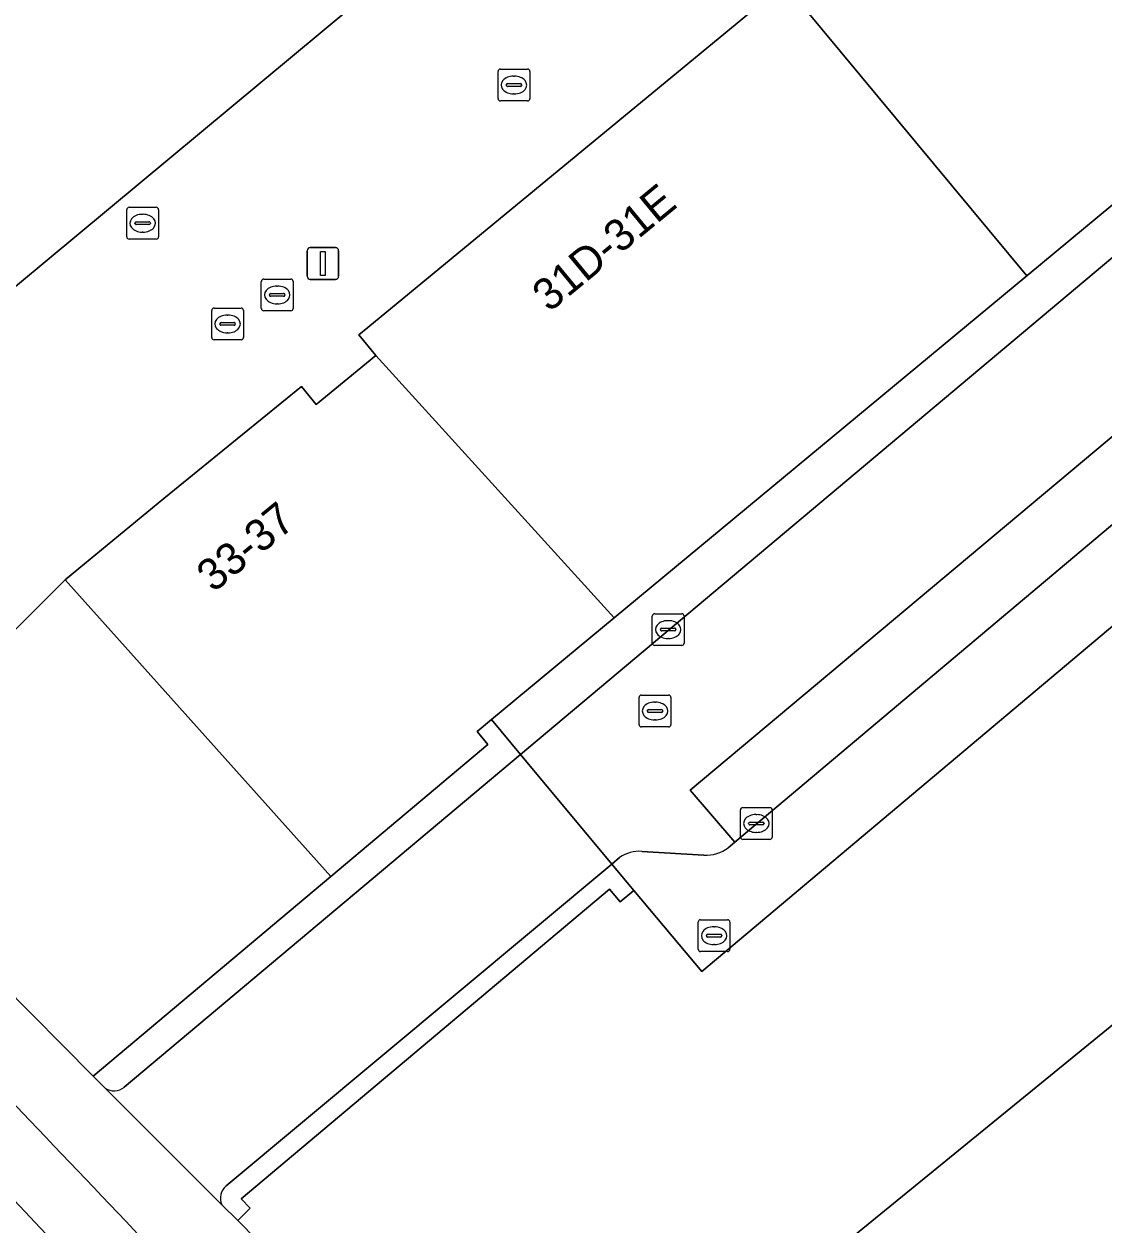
# Model space of a CAD drawing. Extents: x 161087 to 161926, y 382572 to 383873.
# Drawn here: x 161249.19 to 161283.16, y 383145.33 to 383183.09 of the extents above; entities that cross this region are included whole.
import ezdxf

# ---------------------------------------------------------------- set-up
doc = ezdxf.new("R2010")
doc.units = 0
for name, color, linetype in [('IMGEO_Berm_open', 7, 'Continuous'), ('IMGEO_Fietspad_gesloten', 7, 'Continuous'), ('IMGEO_Kolk', 7, 'Continuous'), ('IMGEO_Lichtmast', 7, 'Continuous'), ('IMGEO_Pand', 7, 'Continuous'), ('IMGEO_Pand_nummerreeks', 7, 'Continuous'), ('IMGEO_Pand_overbouw', 7, 'Continuous'), ('IMGEO_Parkeervlak_open', 7, 'Continuous'), ('IMGEO_Rijbaan_lokaal_open', 7, 'Continuous'), ('IMGEO_Rioolput', 7, 'Continuous'), ('IMGEO_Voetgangersgebied_open', 7, 'Continuous'), ('IMGEO_Voetpad_open', 7, 'Continuous')]:
    doc.layers.add(name, color=color, linetype=linetype)

msp = doc.modelspace()

# ---------------------------------------------------------------- linework, layer by layer
at = {"layer": 'IMGEO_Berm_open'}
msp.add_lwpolyline([(161247.064, 383148.001), (161242.001, 383153.229), (161238.837, 383153.269), (161246.469, 383145.394), (161245.035, 383144.043), (161249.891, 383139.013), (161252.834, 383141.869)], close=True, dxfattribs=at)
at = {"layer": 'IMGEO_Fietspad_gesloten'}
msp.add_lwpolyline([(161249.369, 383148.585), (161245.087, 383153.075), (161241.034, 383157.27), (161239.46, 383155.862), (161242.001, 383153.229), (161247.064, 383148.001), (161252.834, 383141.869), (161255.215, 383139.338), (161259.245, 383134.997), (161263.4, 383130.521)], dxfattribs=at)
msp.add_arc((160590.35, 382517.9), 912.178, 42.27546, 43.741408, dxfattribs=at)
at = {"layer": 'IMGEO_Kolk'}
for p, q in [((161264.101, 383180.745), (161264.101, 383181.597)), ((161264.176, 383181.671), (161265.028, 383181.671)), ((161265.102, 383181.597), (161265.102, 383180.745)), ((161264.36, 383181.165), (161264.36, 383181.177)), ((161264.403, 383181.214), (161264.801, 383181.214)), ((161264.589, 383181.451), (161264.614, 383181.451)), ((161264.844, 383181.177), (161264.844, 383181.165)), ((161264.798, 383181.128), (161264.4, 383181.128)), ((161264.612, 383180.891), (161264.587, 383180.891)), ((161265.028, 383180.671), (161264.176, 383180.671)), ((161252.419, 383176.396), (161252.419, 383177.248)), ((161252.494, 383177.322), (161253.346, 383177.322)), ((161252.907, 383177.102), (161252.932, 383177.102)), ((161253.42, 383177.248), (161253.42, 383176.396)), ((161252.678, 383176.816), (161252.678, 383176.828)), ((161253.116, 383176.779), (161252.718, 383176.779)), ((161252.721, 383176.865), (161253.119, 383176.865)), ((161253.162, 383176.828), (161253.162, 383176.816)), ((161253.346, 383176.322), (161252.494, 383176.322)), ((161252.93, 383176.542), (161252.905, 383176.542)), ((161255.091, 383173.226), (161255.091, 383174.078)), ((161255.166, 383174.152), (161256.018, 383174.152)), ((161256.092, 383174.078), (161256.092, 383173.226)), ((161255.35, 383173.646), (161255.35, 383173.658)), ((161255.788, 383173.609), (161255.39, 383173.609)), ((161255.393, 383173.695), (161255.791, 383173.695)), ((161255.579, 383173.932), (161255.604, 383173.932)), ((161255.834, 383173.658), (161255.834, 383173.646)), ((161255.602, 383173.372), (161255.577, 383173.372)), ((161256.018, 383173.152), (161255.166, 383173.152)), ((161268.953, 383163.609), (161268.953, 383164.461)), ((161269.028, 383164.535), (161269.88, 383164.535)), ((161269.441, 383164.315), (161269.466, 383164.315)), ((161269.954, 383164.461), (161269.954, 383163.609)), ((161269.212, 383164.029), (161269.212, 383164.041)), ((161269.65, 383163.992), (161269.252, 383163.992)), ((161269.255, 383164.078), (161269.653, 383164.078)), ((161269.696, 383164.041), (161269.696, 383164.029)), ((161269.88, 383163.535), (161269.028, 383163.535)), ((161269.464, 383163.755), (161269.439, 383163.755)), ((161271.726, 383157.507), (161271.726, 383158.359)), ((161271.801, 383158.433), (161272.653, 383158.433)), ((161272.214, 383158.213), (161272.239, 383158.213)), ((161272.727, 383158.359), (161272.727, 383157.507)), ((161271.985, 383157.927), (161271.985, 383157.939)), ((161272.423, 383157.89), (161272.025, 383157.89)), ((161272.028, 383157.976), (161272.426, 383157.976)), ((161272.469, 383157.939), (161272.469, 383157.927)), ((161272.653, 383157.433), (161271.801, 383157.433)), ((161272.237, 383157.653), (161272.212, 383157.653))]:
    msp.add_line(p, q, dxfattribs=at)
for points in [[(161264.101, 383180.745), (161264.101, 383181.597)], [(161264.176, 383181.671), (161265.028, 383181.671)], [(161265.102, 383181.597), (161265.102, 383180.745)], [(161265.028, 383180.671), (161264.176, 383180.671)], [(161252.419, 383176.396), (161252.419, 383177.248)], [(161252.494, 383177.322), (161253.346, 383177.322)], [(161253.42, 383177.248), (161253.42, 383176.396)], [(161253.346, 383176.322), (161252.494, 383176.322)], [(161255.091, 383173.226), (161255.091, 383174.078)], [(161255.166, 383174.152), (161256.018, 383174.152)], [(161256.092, 383174.078), (161256.092, 383173.226)], [(161256.018, 383173.152), (161255.166, 383173.152)], [(161268.953, 383163.609), (161268.953, 383164.461)], [(161269.028, 383164.535), (161269.88, 383164.535)], [(161269.954, 383164.461), (161269.954, 383163.609)], [(161269.88, 383163.535), (161269.028, 383163.535)], [(161271.726, 383157.507), (161271.726, 383158.359)], [(161271.801, 383158.433), (161272.653, 383158.433)], [(161272.727, 383158.359), (161272.727, 383157.507)], [(161272.653, 383157.433), (161271.801, 383157.433)]]:
    msp.add_lwpolyline(points, dxfattribs=at)
for centre, radius, start, end in [((161264.178, 383181.595), 0.0765, 91.552, 178.448), ((161264.178, 383181.595), 0.0765, 91.552, 178.448), ((161265.026, 383181.595), 0.0765, 1.552, 88.448), ((161265.026, 383181.595), 0.0765, 1.552, 88.448), ((161264.4, 383181.174), 0.0403, 85.8775, 175.7526), ((161264.397, 383181.164), 0.0366, 178.938, 274.7102), ((161264.801, 383181.171), 0.043, 264.8664, 352.4533), ((161264.805, 383181.176), 0.0386, 1.7309, 96.639), ((161264.178, 383180.747), 0.0765, 181.552, 268.448), ((161264.178, 383180.747), 0.0765, 181.552, 268.448), ((161265.026, 383180.747), 0.0765, 271.552, 358.448), ((161265.026, 383180.747), 0.0765, 271.552, 358.448), ((161252.496, 383177.246), 0.0765, 91.552, 178.448), ((161252.496, 383177.246), 0.0765, 91.552, 178.448), ((161253.344, 383177.246), 0.0765, 1.552, 88.448), ((161253.344, 383177.246), 0.0765, 1.552, 88.448), ((161252.718, 383176.825), 0.0403, 85.8775, 175.7526), ((161252.715, 383176.815), 0.0366, 178.938, 274.7102), ((161253.119, 383176.822), 0.043, 264.8664, 352.4533), ((161253.123, 383176.827), 0.0386, 1.7309, 96.639), ((161252.496, 383176.398), 0.0765, 181.552, 268.448), ((161252.496, 383176.398), 0.0765, 181.552, 268.448), ((161253.344, 383176.398), 0.0765, 271.552, 358.448), ((161253.344, 383176.398), 0.0765, 271.552, 358.448), ((161255.168, 383174.076), 0.0765, 91.552, 178.448), ((161255.168, 383174.076), 0.0765, 91.552, 178.448), ((161256.016, 383174.076), 0.0765, 1.552, 88.448), ((161256.016, 383174.076), 0.0765, 1.552, 88.448), ((161255.39, 383173.655), 0.0403, 85.8775, 175.7526), ((161255.387, 383173.645), 0.0366, 178.938, 274.7102), ((161255.791, 383173.652), 0.043, 264.8664, 352.4533), ((161255.795, 383173.657), 0.0386, 1.7309, 96.639), ((161255.168, 383173.228), 0.0765, 181.552, 268.448), ((161255.168, 383173.228), 0.0765, 181.552, 268.448), ((161256.016, 383173.228), 0.0765, 271.552, 358.448), ((161256.016, 383173.228), 0.0765, 271.552, 358.448), ((161269.03, 383164.459), 0.0765, 91.552, 178.448), ((161269.03, 383164.459), 0.0765, 91.552, 178.448), ((161269.878, 383164.459), 0.0765, 1.552, 88.448), ((161269.878, 383164.459), 0.0765, 1.552, 88.448), ((161269.252, 383164.038), 0.0403, 85.8775, 175.7526), ((161269.249, 383164.028), 0.0366, 178.938, 274.7102), ((161269.653, 383164.035), 0.043, 264.8664, 352.4533), ((161269.657, 383164.04), 0.0386, 1.7309, 96.639), ((161269.03, 383163.611), 0.0765, 181.552, 268.448), ((161269.03, 383163.611), 0.0765, 181.552, 268.448), ((161269.878, 383163.611), 0.0765, 271.552, 358.448), ((161269.878, 383163.611), 0.0765, 271.552, 358.448), ((161271.803, 383158.357), 0.0765, 91.552, 178.448), ((161271.803, 383158.357), 0.0765, 91.552, 178.448), ((161272.651, 383158.357), 0.0765, 1.552, 88.448), ((161272.651, 383158.357), 0.0765, 1.552, 88.448), ((161272.025, 383157.936), 0.0403, 85.8775, 175.7526), ((161272.022, 383157.926), 0.0366, 178.938, 274.7102), ((161272.426, 383157.933), 0.043, 264.8664, 352.4533), ((161272.43, 383157.938), 0.0386, 1.7309, 96.639), ((161271.803, 383157.509), 0.0765, 181.552, 268.448), ((161271.803, 383157.509), 0.0765, 181.552, 268.448), ((161272.651, 383157.509), 0.0765, 271.552, 358.448), ((161272.651, 383157.509), 0.0765, 271.552, 358.448)]:
    msp.add_arc(centre, radius, start, end, dxfattribs=at)
for centre, major_axis, ratio, start_param, end_param in [((161264.588, 383181.171), (-0.387, 0.002), 0.722429, 4.712389, 7.853982), ((161264.613, 383181.171), (-0.39, 0.002), 0.717154, 1.570796, 4.712389), ((161252.906, 383176.822), (-0.387, 0.002), 0.722429, 4.712389, 7.853982), ((161252.931, 383176.822), (-0.39, 0.002), 0.717154, 1.570796, 4.712389), ((161255.578, 383173.652), (-0.387, 0.002), 0.722429, 4.712389, 7.853982), ((161255.603, 383173.652), (-0.39, 0.002), 0.717154, 1.570796, 4.712389), ((161269.44, 383164.035), (-0.387, 0.002), 0.722429, 4.712389, 7.853982), ((161269.465, 383164.035), (-0.39, 0.002), 0.717154, 1.570796, 4.712389), ((161272.213, 383157.933), (-0.387, 0.002), 0.722429, 4.712389, 7.853982), ((161272.238, 383157.933), (-0.39, 0.002), 0.717154, 1.570796, 4.712389)]:
    msp.add_ellipse(centre, major_axis=major_axis, ratio=ratio, start_param=start_param, end_param=end_param, dxfattribs=at)
at = {"layer": 'IMGEO_Lichtmast'}
for p, q in [((161258.094, 383175.156), (161258.094, 383175.956)), ((161258.094, 383175.956), (161258.094, 383175.156)), ((161258.194, 383176.056), (161258.984, 383176.056)), ((161258.984, 383176.056), (161258.194, 383176.056)), ((161259.084, 383175.956), (161259.084, 383175.156)), ((161259.084, 383175.156), (161259.084, 383175.956)), ((161258.984, 383175.056), (161258.194, 383175.056)), ((161258.194, 383175.056), (161258.984, 383175.056))]:
    msp.add_line(p, q, dxfattribs=at)
msp.add_lwpolyline([(161258.514, 383175.931), (161258.664, 383175.931), (161258.664, 383175.181), (161258.514, 383175.181), (161258.514, 383175.931)], dxfattribs=at)
for centre, start, end in [((161258.194, 383175.956), 90, 180), ((161258.194, 383175.956), 90, 180), ((161258.984, 383175.956), 0, 90), ((161258.984, 383175.956), 360, 90), ((161258.194, 383175.156), 180, 270), ((161258.194, 383175.156), 180, 270), ((161258.984, 383175.156), 270, 0), ((161258.984, 383175.156), 270, 0)]:
    msp.add_arc(centre, 0.1, start, end, dxfattribs=at)
at = {"layer": 'IMGEO_Pand'}
msp.add_lwpolyline([(161247.047, 383173.276), (161266.225, 383189.236), (161268.612, 383191.223), (161267.433, 383193.115), (161266.263, 383194.991), (161266.902, 383195.411), (161267.206, 383194.975), (161269.105, 383196.169), (161268.823, 383196.651), (161269.671, 383197.207), (161269.811, 383197.458)], dxfattribs=at)
for points in [[(161280.736, 383175.169), (161291.129, 383183.787), (161293.2, 383185.53), (161285.527, 383194.6), (161273.115, 383184.359)], [(161280.736, 383175.169), (161273.115, 383184.359), (161259.999, 383173.538), (161259.721, 383173.308), (161260.256, 383172.66), (161267.754, 383164.404)], [(161258.837, 383156.265), (161263.783, 383160.421), (161263.444, 383160.83), (161263.899, 383161.207), (161267.754, 383164.404), (161260.256, 383172.66), (161258.381, 383171.113), (161257.912, 383171.681), (161253.589, 383168.159), (161250.731, 383165.806), (161250.478, 383165.598)], [(161264.781, 383136.382), (161291.307, 383158.02), (161298.29, 383163.897), (161297.775, 383164.509), (161292.01, 383171.36), (161270.516, 383153.271), (161268.369, 383155.821), (161267.947, 383155.467), (161267.612, 383155.865), (161256.015, 383146.119), (161256.302, 383145.826), (161255.909, 383145.44), (161264.4, 383136.806)], [(161258.837, 383156.265), (161250.478, 383165.598), (161243.155, 383158.284), (161246.206, 383155.197), (161248.463, 383152.913), (161251.359, 383149.983)], [(161297.168, 383151.056), (161291.307, 383158.02), (161264.781, 383136.382), (161270.69, 383129.816), (161270.593, 383129.53), (161270.694, 383129.417), (161283.857, 383139.854)]]:
    msp.add_lwpolyline(points, close=True, dxfattribs=at)
at = {"layer": 'IMGEO_Pand_overbouw'}
msp.add_lwpolyline([(161258.837, 383156.265), (161251.359, 383149.983), (161251.737, 383149.606), (161255.415, 383145.933), (161255.909, 383145.44), (161256.302, 383145.826), (161256.015, 383146.119), (161267.612, 383155.865), (161267.947, 383155.467), (161268.369, 383155.821), (161267.679, 383156.652), (161264.811, 383160.108), (161263.899, 383161.207), (161263.444, 383160.83), (161263.783, 383160.421)], close=True, dxfattribs=at)
at = {"layer": 'IMGEO_Parkeervlak_open'}
msp.add_lwpolyline([(161271.553, 383157.342), (161288.65, 383171.732), (161287.273, 383173.334), (161270.148, 383158.986)], close=True, dxfattribs=at)
at = {"layer": 'IMGEO_Rijbaan_lokaal_open'}
for points in [[(161287.56, 383179.213), (161264.811, 383160.108), (161267.679, 383156.652), (161267.925, 383156.857)], [(161271.345, 383157.167), (161271.553, 383157.342), (161270.148, 383158.986), (161287.273, 383173.334), (161288.65, 383171.732), (161289.78, 383172.684)], [(161255.549, 383146.528), (161267.679, 383156.652), (161264.811, 383160.108), (161252.343, 383149.638)], [(161268.627, 383157.055), (161270.574, 383156.94)], [(161251.737, 383149.606), (161255.415, 383145.933)]]:
    msp.add_lwpolyline(points, dxfattribs=at)
for centre, radius, start, end in [((161268.53, 383156.057), 1.003, 84.421, 127.0813), ((161270.655, 383158.088), 1.151, 265.9631, 306.8482), ((161252.019, 383150.026), 0.506, 236.1588, 309.8867), ((161255.843, 383146.149), 0.479, 127.7881, 206.8282)]:
    msp.add_arc(centre, radius, start, end, dxfattribs=at)
at = {"layer": 'IMGEO_Rioolput'}
for p, q in [((161256.653, 383174.139), (161256.653, 383174.991)), ((161256.728, 383175.065), (161257.58, 383175.065)), ((161257.141, 383174.845), (161257.166, 383174.845)), ((161257.654, 383174.991), (161257.654, 383174.139)), ((161256.912, 383174.559), (161256.912, 383174.571)), ((161257.35, 383174.522), (161256.952, 383174.522)), ((161256.955, 383174.608), (161257.353, 383174.608)), ((161257.396, 383174.571), (161257.396, 383174.559)), ((161257.58, 383174.065), (161256.728, 383174.065)), ((161257.164, 383174.285), (161257.139, 383174.285)), ((161268.538, 383161.046), (161268.538, 383161.898)), ((161268.613, 383161.972), (161269.465, 383161.972)), ((161269.539, 383161.898), (161269.539, 383161.046)), ((161269.026, 383161.752), (161269.051, 383161.752)), ((161268.797, 383161.466), (161268.797, 383161.478)), ((161269.235, 383161.429), (161268.837, 383161.429)), ((161268.84, 383161.515), (161269.238, 383161.515)), ((161269.049, 383161.192), (161269.024, 383161.192)), ((161269.281, 383161.478), (161269.281, 383161.466)), ((161269.465, 383160.972), (161268.613, 383160.972)), ((161270.396, 383153.976), (161270.396, 383154.828)), ((161270.471, 383154.902), (161271.323, 383154.902)), ((161271.397, 383154.828), (161271.397, 383153.976)), ((161270.655, 383154.396), (161270.655, 383154.408)), ((161271.093, 383154.359), (161270.695, 383154.359)), ((161270.698, 383154.445), (161271.096, 383154.445)), ((161270.884, 383154.682), (161270.909, 383154.682)), ((161271.139, 383154.408), (161271.139, 383154.396)), ((161270.907, 383154.122), (161270.882, 383154.122)), ((161271.323, 383153.902), (161270.471, 383153.902))]:
    msp.add_line(p, q, dxfattribs=at)
for points in [[(161256.653, 383174.139), (161256.653, 383174.991)], [(161256.728, 383175.065), (161257.58, 383175.065)], [(161257.654, 383174.991), (161257.654, 383174.139)], [(161257.58, 383174.065), (161256.728, 383174.065)], [(161268.538, 383161.046), (161268.538, 383161.898)], [(161268.613, 383161.972), (161269.465, 383161.972)], [(161269.539, 383161.898), (161269.539, 383161.046)], [(161269.465, 383160.972), (161268.613, 383160.972)], [(161270.396, 383153.976), (161270.396, 383154.828)], [(161270.471, 383154.902), (161271.323, 383154.902)], [(161271.397, 383154.828), (161271.397, 383153.976)], [(161271.323, 383153.902), (161270.471, 383153.902)]]:
    msp.add_lwpolyline(points, dxfattribs=at)
for centre, radius, start, end in [((161256.73, 383174.989), 0.0765, 91.552, 178.448), ((161256.73, 383174.989), 0.0765, 91.552, 178.448), ((161257.578, 383174.989), 0.0765, 1.552, 88.448), ((161257.578, 383174.989), 0.0765, 1.552, 88.448), ((161256.952, 383174.568), 0.0403, 85.8775, 175.7526), ((161256.949, 383174.558), 0.0366, 178.938, 274.7102), ((161257.353, 383174.565), 0.043, 264.8664, 352.4533), ((161257.357, 383174.57), 0.0386, 1.7309, 96.639), ((161256.73, 383174.141), 0.0765, 181.552, 268.448), ((161256.73, 383174.141), 0.0765, 181.552, 268.448), ((161257.578, 383174.141), 0.0765, 271.552, 358.448), ((161257.578, 383174.141), 0.0765, 271.552, 358.448), ((161268.615, 383161.896), 0.0765, 91.552, 178.448), ((161268.615, 383161.896), 0.0765, 91.552, 178.448), ((161269.463, 383161.896), 0.0765, 1.552, 88.448), ((161269.463, 383161.896), 0.0765, 1.552, 88.448), ((161268.837, 383161.475), 0.0403, 85.8775, 175.7526), ((161268.834, 383161.465), 0.0366, 178.938, 274.7102), ((161269.238, 383161.472), 0.043, 264.8664, 352.4533), ((161269.242, 383161.477), 0.0386, 1.7309, 96.639), ((161268.615, 383161.048), 0.0765, 181.552, 268.448), ((161268.615, 383161.048), 0.0765, 181.552, 268.448), ((161269.463, 383161.048), 0.0765, 271.552, 358.448), ((161269.463, 383161.048), 0.0765, 271.552, 358.448), ((161270.473, 383154.826), 0.0765, 91.552, 178.448), ((161270.473, 383154.826), 0.0765, 91.552, 178.448), ((161271.321, 383154.826), 0.0765, 1.552, 88.448), ((161271.321, 383154.826), 0.0765, 1.552, 88.448), ((161270.695, 383154.405), 0.0403, 85.8775, 175.7526), ((161270.692, 383154.395), 0.0366, 178.938, 274.7102), ((161271.096, 383154.402), 0.043, 264.8664, 352.4533), ((161271.1, 383154.407), 0.0386, 1.7309, 96.639), ((161270.473, 383153.978), 0.0765, 181.552, 268.448), ((161270.473, 383153.978), 0.0765, 181.552, 268.448), ((161271.321, 383153.978), 0.0765, 271.552, 358.448), ((161271.321, 383153.978), 0.0765, 271.552, 358.448)]:
    msp.add_arc(centre, radius, start, end, dxfattribs=at)
for centre, major_axis, ratio, start_param, end_param in [((161257.14, 383174.565), (-0.387, 0.002), 0.722429, 4.712389, 7.853982), ((161257.165, 383174.565), (-0.39, 0.002), 0.717154, 1.570796, 4.712389), ((161269.025, 383161.472), (-0.387, 0.002), 0.722429, 4.712389, 7.853982), ((161269.05, 383161.472), (-0.39, 0.002), 0.717154, 1.570796, 4.712389), ((161270.883, 383154.402), (-0.387, 0.002), 0.722429, 4.712389, 7.853982), ((161270.908, 383154.402), (-0.39, 0.002), 0.717154, 1.570796, 4.712389)]:
    msp.add_ellipse(centre, major_axis=major_axis, ratio=ratio, start_param=start_param, end_param=end_param, dxfattribs=at)
at = {"layer": 'IMGEO_Voetgangersgebied_open'}
for points in [[(161243.155, 383158.284), (161250.478, 383165.598), (161250.731, 383165.806), (161253.589, 383168.159), (161257.912, 383171.681), (161258.381, 383171.113), (161260.256, 383172.66), (161259.721, 383173.308), (161259.999, 383173.538), (161273.115, 383184.359), (161285.527, 383194.6), (161291.164, 383199.251), (161292.631, 383200.461), (161292.589, 383200.711), (161293.108, 383201.139), (161293.29, 383200.927), (161296.791, 383203.457), (161296.427, 383204.1), (161299.212, 383206.349), (161303.92, 383210.151)], [(161269.811, 383197.458), (161269.671, 383197.207), (161268.823, 383196.651), (161269.105, 383196.169), (161267.206, 383194.975), (161266.902, 383195.411), (161266.263, 383194.991), (161267.433, 383193.115), (161268.612, 383191.223), (161266.225, 383189.236), (161247.047, 383173.276)]]:
    msp.add_lwpolyline(points, dxfattribs=at)
at = {"layer": 'IMGEO_Voetpad_open'}
for points in [[(161307.359, 383184.167), (161305.277, 383186.646), (161297.669, 383180.243), (161295.441, 383182.891), (161293.2, 383185.53), (161291.129, 383183.787), (161280.736, 383175.169), (161267.754, 383164.404), (161263.899, 383161.207), (161264.811, 383160.108), (161287.56, 383179.213)], [(161289.78, 383172.684), (161288.65, 383171.732), (161271.553, 383157.342), (161271.345, 383157.167)], [(161267.925, 383156.857), (161267.679, 383156.652), (161268.369, 383155.821), (161270.516, 383153.271), (161292.01, 383171.36), (161292.897, 383172.092), (161292.606, 383172.442)], [(161252.343, 383149.638), (161264.811, 383160.108), (161263.899, 383161.207), (161263.444, 383160.83), (161263.783, 383160.421), (161258.837, 383156.265), (161251.359, 383149.983), (161251.737, 383149.606)], [(161270.574, 383156.94), (161268.627, 383157.055)], [(161255.415, 383145.933), (161255.909, 383145.44), (161256.302, 383145.826), (161256.015, 383146.119), (161267.612, 383155.865), (161267.947, 383155.467), (161268.369, 383155.821), (161267.679, 383156.652), (161255.549, 383146.528)], [(161245.087, 383153.075), (161249.369, 383148.585)], [(161285.682, 383112.035), (161286.895, 383113.101), (161286.136, 383113.965), (161285.039, 383113), (161284.685, 383113.393), (161281.451, 383116.982), (161281.517, 383117.177), (161280.814, 383117.977), (161280.692, 383117.869), (161280.343, 383118.266), (161280.485, 383118.391), (161277.623, 383121.614), (161270.694, 383129.417), (161270.593, 383129.53), (161270.69, 383129.816), (161264.781, 383136.382), (161264.4, 383136.806), (161255.909, 383145.44), (161255.415, 383145.933), (161251.737, 383149.606), (161251.359, 383149.983), (161248.463, 383152.913)]]:
    msp.add_lwpolyline(points, dxfattribs=at)
for centre, radius, start, end in [((161268.53, 383156.057), 1.003, 84.421, 127.0813), ((161270.655, 383158.088), 1.151, 265.9631, 306.8482), ((161252.019, 383150.026), 0.506, 236.1588, 309.8867), ((160590.35, 382517.9), 912.178, 42.27546, 43.741408), ((161255.843, 383146.149), 0.479, 127.7881, 206.8282)]:
    msp.add_arc(centre, radius, start, end, dxfattribs=at)

# ---------------------------------------------------------------- texts
at = {"layer": 'IMGEO_Pand_nummerreeks'}
for s, rotation, p in [('31D-31E', 39.525, (161265.711, 383173.998)), ('33-37', 39.2663, (161255.145, 383165.177))]:
    msp.add_text(s, height=1, rotation=rotation, dxfattribs=at).set_placement(p)

doc.saveas('drawing.dxf')
